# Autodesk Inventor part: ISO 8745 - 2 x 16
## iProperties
Created: 2004-01
Part Number: ISO 8745 - 2 x 16
Material: Standard
Catalog Web Link: file:///C:/Programme/Autodesk/Inventor 5.3/Content/Din/index.htm?doNavigateId=DF1221CC-CB3D-11D4-A9FB-0080AD303E0A|0557BE4BB16611D4BA6900C04F798F98|true
Description: Kerbstift
Document SubType Name: Standard Catalog Part
Standard: ISO 8745 - 2 x 16
Designer: Ulrich
Control State: 0
Master: False
Checked Out: False
Shininess: 20.0
Angle Display Precision: 2
Document Length Units: 11269
Document Angle Units: 11279
Document Time Units: 11290
Document Mass Units: 11283
Document Length Units Precision: 3
Document Angle Units Precision: 2
Compacted: True
KLASSIFIKATION: 31163206 un/spsc
HERSTELLER: DIN Normsystem
Density: 0.0
Volumn: 0.0
Area: 0.0
PropertySet Name: Model Information
Author: Ulrich
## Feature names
1. Basis1
